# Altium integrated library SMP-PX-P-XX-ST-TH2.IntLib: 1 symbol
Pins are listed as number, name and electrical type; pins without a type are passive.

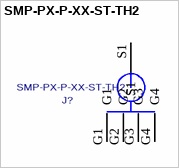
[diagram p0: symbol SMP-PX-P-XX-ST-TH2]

## SMP-PX-P-XX-ST-TH2
designator J?
SMP THROUGH HOLE PLUG - 50 OHM.; MANUFACTURER: SAMTEC
footprint SMP-PF-P-XX-ST-TH2
pins: G1, G2, G3, G4, S1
